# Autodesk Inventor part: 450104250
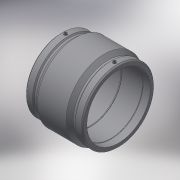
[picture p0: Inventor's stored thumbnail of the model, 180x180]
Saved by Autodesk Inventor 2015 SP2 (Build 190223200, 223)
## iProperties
Created: 2017-06
Part Number: 450104250
Material: Generic
Description: PLASSON COUPLER 250 PN25
Document SubType Name: Modeling
Designer: KIM
Mass: 8622.19 g
Surface Area: 6772.47 cm^2
Volume: 8622.19 cm^3
Density: 1 g/cm^3
Appearance: Default
Author: KIM
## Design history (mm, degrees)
derived "450104.ipt"
feature "Solid1::450104.ipt"
tag "TaggingFeature1"
body "Solid1"
other parameters: "d0" = 256, "d3" = 127, "d4" = 64, "d5" = 279, "d8" = 168 deg, "d10" = 50.8, "d11" = 16.93333, "d13" = 256, "d14" = 17.6296, "d15" = 127, "d16" = 127, "d17" = 247.5, "d19" = 3.52592, "d20" = 168 deg, "d22" = 291.4, "d24" = 282.658, "d25" = 135 deg, "d26" = 128, "d27" = 135 deg, "d29" = 155, "d30" = 15, "d31" = 89.6, "d34" = 5 deg, "d35" = 15, "d39" = 5 deg, "d41" = 4, "d42" = 14, "d43" = 0, "d45" = 4, "d46" = 14, "d47" = 0, "d48" = 3, "d49" = 0, "d50" = 3, "d51" = 0, "d52" = 36.83, "d53" = 9.2075, "L_" = 256, "L_1" = 127, "A_" = 155, "d_2" = 12
